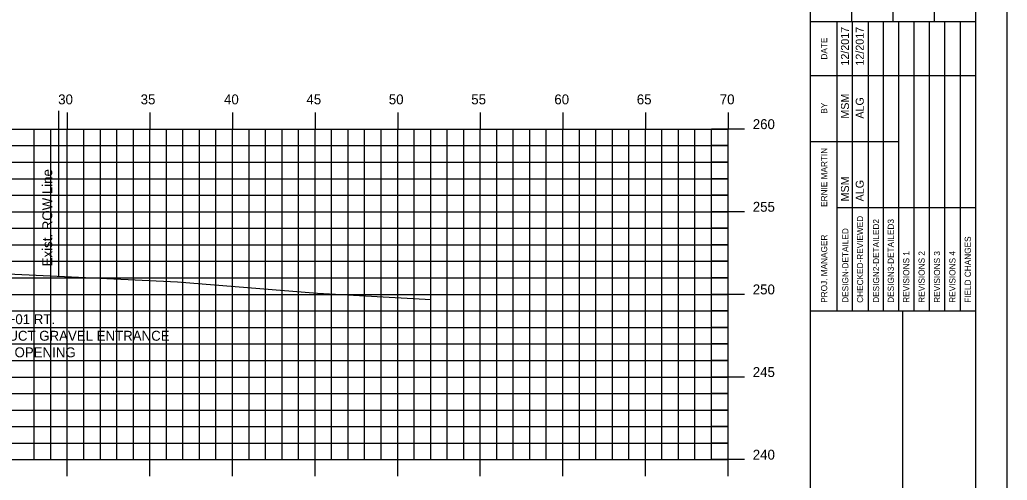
# Model space of a CAD drawing. Extents: x 859129 to 859299, y 366268 to 366378.
# Drawn here: x 859239.6 to 859299.4, y 366306 to 366333.9 of the extents above; entities that cross this region are included whole.
import ezdxf

# ---------------------------------------------------------------- set-up
doc = ezdxf.new("R2010")
doc.units = 0
for name, color, linetype in [('ANNOTATION', 7, 'Continuous'), ('BORDER', 7, 'Continuous'), ('E_ROW_Line', 7, 'Continuous'), ('H_V ANNOTATION', 7, 'Continuous'), ('MAJOR', 7, 'Continuous'), ('MINOR', 7, 'Continuous'), ('PLOT BOUNDARY', 7, 'Continuous'), ('S_Roadway_Centerline', 7, 'Continuous')]:
    doc.layers.add(name, color=color, linetype=linetype)

msp = doc.modelspace()

# ---------------------------------------------------------------- linework, layer by layer
at = {"layer": 'BORDER'}
for p, q in [((859287.462, 366271.236), (859287.462, 366376.239)), ((859297.462, 366271.236), (859297.462, 366376.236)), ((859289.962, 366333.739), (859289.962, 366342.387)), ((859292.462, 366333.739), (859292.462, 366342.387)), ((859294.962, 366333.739), (859294.962, 366342.387)), ((859287.462, 366333.739), (859297.462, 366333.739)), ((859287.462, 366316.239), (859297.462, 366316.239)), ((859293.053, 366281.239), (859293.053, 366316.239))]:
    msp.add_line(p, q, dxfattribs=at)
for points in [[(859289.077, 366330.489), (859289.077, 366333.739)], [(859290.009, 366316.242), (859290.009, 366333.739)], [(859290.941, 366333.739), (859290.941, 366316.242)], [(859291.873, 366316.242), (859291.873, 366333.739)], [(859292.804, 366316.242), (859292.804, 366333.739)], [(859293.736, 366316.242), (859293.736, 366333.739)], [(859294.668, 366316.242), (859294.668, 366333.739)], [(859295.599, 366316.242), (859295.599, 366333.739)], [(859296.531, 366316.242), (859296.531, 366333.739)], [(859289.078, 366316.242), (859289.078, 366333.033)], [(859287.462, 366330.489), (859297.462, 366330.489)], [(859287.462, 366326.489), (859289.078, 366326.489)], [(859289.077, 366326.489), (859292.803, 366326.489)], [(859289.077, 366322.489), (859297.462, 366322.489)]]:
    msp.add_lwpolyline(points, dxfattribs=at)
at = {"layer": 'E_ROW_Line'}
msp.add_line((859241.95, 366318.333), (859241.95, 366328.333), dxfattribs=at)
at = {"layer": 'MAJOR'}
for p, q in [((859242.462, 366328.238), (859242.462, 366327.236)), ((859247.462, 366328.238), (859247.462, 366327.236)), ((859252.462, 366328.238), (859252.462, 366327.236)), ((859257.462, 366328.238), (859257.462, 366327.236)), ((859262.462, 366328.238), (859262.462, 366327.236)), ((859267.462, 366328.238), (859267.462, 366327.236)), ((859272.462, 366328.238), (859272.462, 366327.236)), ((859277.462, 366328.238), (859277.462, 366327.236)), ((859282.462, 366328.238), (859282.462, 366327.236)), ((859142.462, 366327.236), (859282.462, 366327.236)), ((859142.462, 366327.236), (859282.462, 366327.236)), ((859242.462, 366307.236), (859242.462, 366327.236)), ((859247.462, 366307.236), (859247.462, 366327.236)), ((859252.462, 366307.236), (859252.462, 366327.236)), ((859257.462, 366307.236), (859257.462, 366327.236)), ((859262.462, 366307.236), (859262.462, 366327.236)), ((859267.462, 366307.236), (859267.462, 366327.236)), ((859272.462, 366307.236), (859272.462, 366327.236)), ((859277.462, 366307.236), (859277.462, 366327.236)), ((859283.464, 366327.236), (859281.46, 366327.236)), ((859282.462, 366307.236), (859282.462, 366327.236)), ((859282.462, 366307.236), (859282.462, 366327.236)), ((859142.462, 366322.236), (859282.462, 366322.236)), ((859283.464, 366322.236), (859281.46, 366322.236)), ((859142.462, 366317.236), (859282.462, 366317.236)), ((859283.464, 366317.236), (859281.46, 366317.236)), ((859142.462, 366312.236), (859282.462, 366312.236)), ((859283.464, 366312.236), (859281.46, 366312.236)), ((859142.462, 366307.236), (859282.462, 366307.236)), ((859142.462, 366307.236), (859282.462, 366307.236)), ((859242.462, 366306.234), (859242.462, 366307.236)), ((859247.462, 366306.234), (859247.462, 366307.236)), ((859252.462, 366306.234), (859252.462, 366307.236)), ((859257.462, 366306.234), (859257.462, 366307.236)), ((859262.462, 366306.234), (859262.462, 366307.236)), ((859267.462, 366306.234), (859267.462, 366307.236)), ((859272.462, 366306.234), (859272.462, 366307.236)), ((859277.462, 366306.234), (859277.462, 366307.236)), ((859283.464, 366307.236), (859281.46, 366307.236)), ((859282.462, 366306.234), (859282.462, 366307.236))]:
    msp.add_line(p, q, dxfattribs=at)
at = {"layer": 'MINOR'}
for p, q in [((859240.462, 366307.236), (859240.462, 366327.236)), ((859241.462, 366307.236), (859241.462, 366327.236)), ((859243.462, 366307.236), (859243.462, 366327.236)), ((859244.462, 366307.236), (859244.462, 366327.236)), ((859245.462, 366307.236), (859245.462, 366327.236)), ((859246.462, 366307.236), (859246.462, 366327.236)), ((859248.462, 366307.236), (859248.462, 366327.236)), ((859249.462, 366307.236), (859249.462, 366327.236)), ((859250.462, 366307.236), (859250.462, 366327.236)), ((859251.462, 366307.236), (859251.462, 366327.236)), ((859253.462, 366307.236), (859253.462, 366327.236)), ((859254.462, 366307.236), (859254.462, 366327.236)), ((859255.462, 366307.236), (859255.462, 366327.236)), ((859256.462, 366307.236), (859256.462, 366327.236)), ((859258.462, 366307.236), (859258.462, 366327.236)), ((859259.462, 366307.236), (859259.462, 366327.236)), ((859260.462, 366307.236), (859260.462, 366327.236)), ((859261.462, 366307.236), (859261.462, 366327.236)), ((859263.462, 366307.236), (859263.462, 366327.236)), ((859264.462, 366307.236), (859264.462, 366327.236)), ((859265.462, 366307.236), (859265.462, 366327.236)), ((859266.462, 366307.236), (859266.462, 366327.236)), ((859268.462, 366307.236), (859268.462, 366327.236)), ((859269.462, 366307.236), (859269.462, 366327.236)), ((859270.462, 366307.236), (859270.462, 366327.236)), ((859271.462, 366307.236), (859271.462, 366327.236)), ((859273.462, 366307.236), (859273.462, 366327.236)), ((859274.462, 366307.236), (859274.462, 366327.236)), ((859275.462, 366307.236), (859275.462, 366327.236)), ((859276.462, 366307.236), (859276.462, 366327.236)), ((859278.462, 366307.236), (859278.462, 366327.236)), ((859279.462, 366307.236), (859279.462, 366327.236)), ((859280.462, 366307.236), (859280.462, 366327.236)), ((859281.462, 366307.236), (859281.462, 366327.236)), ((859142.462, 366326.236), (859282.462, 366326.236)), ((859282.462, 366326.236), (859281.46, 366326.236)), ((859142.462, 366325.236), (859282.462, 366325.236)), ((859282.462, 366325.236), (859281.46, 366325.236)), ((859142.462, 366324.236), (859282.462, 366324.236)), ((859282.462, 366324.236), (859281.46, 366324.236)), ((859142.462, 366323.236), (859282.462, 366323.236)), ((859282.462, 366323.236), (859281.46, 366323.236)), ((859142.462, 366321.236), (859282.462, 366321.236)), ((859282.462, 366321.236), (859281.46, 366321.236)), ((859142.462, 366320.236), (859282.462, 366320.236)), ((859282.462, 366320.236), (859281.46, 366320.236)), ((859142.462, 366319.236), (859282.462, 366319.236)), ((859282.462, 366319.236), (859281.46, 366319.236)), ((859142.462, 366318.236), (859282.462, 366318.236)), ((859282.462, 366318.236), (859281.46, 366318.236)), ((859142.462, 366316.236), (859282.462, 366316.236)), ((859282.462, 366316.236), (859281.46, 366316.236)), ((859142.462, 366315.236), (859282.462, 366315.236)), ((859282.462, 366315.236), (859281.46, 366315.236)), ((859142.462, 366314.236), (859282.462, 366314.236)), ((859282.462, 366314.236), (859281.46, 366314.236)), ((859142.462, 366313.236), (859282.462, 366313.236)), ((859282.462, 366313.236), (859281.46, 366313.236)), ((859142.462, 366311.236), (859282.462, 366311.236)), ((859282.462, 366311.236), (859281.46, 366311.236)), ((859142.462, 366310.236), (859282.462, 366310.236)), ((859282.462, 366310.236), (859281.46, 366310.236)), ((859142.462, 366309.236), (859282.462, 366309.236)), ((859282.462, 366309.236), (859281.46, 366309.236)), ((859142.462, 366308.236), (859282.462, 366308.236)), ((859282.462, 366308.236), (859281.46, 366308.236))]:
    msp.add_line(p, q, dxfattribs=at)
at = {"layer": 'PLOT BOUNDARY'}
msp.add_lwpolyline([(859129.368, 366268.177), (859299.368, 366268.177), (859299.368, 366378.177), (859129.368, 366378.177)], close=True, dxfattribs=at)
at = {"layer": 'S_Roadway_Centerline'}
msp.add_lwpolyline([(859169.832, 366316.983), (859171.943, 366316.928), (859172.963, 366316.992), (859184.977, 366317.349), (859189.338, 366317.678), (859196.931, 366318.222), (859197.329, 366318.256), (859197.347, 366318.256), (859197.482, 366318.259), (859201.989, 366318.366), (859206.908, 366318.407), (859213.218, 366318.491), (859217.013, 366318.39), (859222.407, 366318.303), (859223.494, 366318.328), (859225.019, 366318.299), (859225.438, 366318.377), (859225.757, 366318.383), (859227.301, 366318.615), (859228.452, 366318.772), (859236.7, 366318.584), (859249.126, 366317.989), (859257.602, 366317.315), (859264.492, 366316.922)], dxfattribs=at)

# ---------------------------------------------------------------- texts
at = {"layer": 'ANNOTATION'}
for s, p in [('STA. 294+01 RT.', (859235.502, 366315.434)), ('CONSTRUCT GRAVEL ENTRANCE', (859235.502, 366314.432)), ("26' CURB OPENING", (859235.502, 366313.43))]:
    msp.add_text(s, height=0.6, dxfattribs=at).set_placement(p)
at = {"layer": 'BORDER'}
for s, height, p in [('12/2017', 0.4845, (859289.785, 366331.081)), ('12/2017', 0.4845, (859290.679, 366331.081)), ('DATE', 0.3714, (859288.466, 366331.445)), ('MSM', 0.4845, (859289.785, 366327.872)), ('ALG', 0.4845, (859290.679, 366327.872)), ('BY', 0.3714, (859288.466, 366328.174)), ('ERNIE MARTIN', 0.37275, (859288.466, 366322.531)), ('MSM', 0.4845, (859289.785, 366322.863)), ('ALG', 0.4845, (859290.679, 366322.863)), ('CHECKED-REVIEWED', 0.37275, (859290.643, 366316.727)), ('DESIGN-DETAILED', 0.37275, (859289.748, 366316.727)), ('DESIGN2-DETAILED2', 0.37275, (859291.612, 366316.727)), ('DESIGN3-DETAILED3', 0.37275, (859292.506, 366316.727)), ('PROJ. MANAGER', 0.37275, (859288.466, 366316.727)), ('FIELD CHANGES', 0.37275, (859297.165, 366316.727)), ('REVISIONS 1', 0.37275, (859293.438, 366316.727)), ('REVISIONS 2', 0.37275, (859294.37, 366316.727)), ('REVISIONS 3', 0.37275, (859295.301, 366316.727)), ('REVISIONS 4', 0.37275, (859296.233, 366316.727))]:
    msp.add_text(s, height=height, rotation=90, dxfattribs=at).set_placement(p)
at = {"layer": 'E_ROW_Line'}
msp.add_text('Exist. ROW Line', height=0.6, rotation=90, dxfattribs=at).set_placement((859241.55, 366318.933))
at = {"layer": 'H_V ANNOTATION'}
for s, p in [('30', (859241.91, 366328.736)), ('35', (859246.902, 366328.736)), ('40', (859251.948, 366328.736)), ('45', (859256.94, 366328.736)), ('50', (859261.926, 366328.736)), ('55', (859266.918, 366328.736)), ('60', (859271.948, 366328.736)), ('65', (859276.94, 366328.736)), ('70', (859281.964, 366328.736)), ('260', (859283.962, 366327.236)), ('255', (859283.962, 366322.236)), ('250', (859283.962, 366317.236)), ('245', (859283.962, 366312.236)), ('240', (859283.962, 366307.236))]:
    msp.add_text(s, height=0.6, dxfattribs=at).set_placement(p)

doc.saveas('drawing.dxf')
